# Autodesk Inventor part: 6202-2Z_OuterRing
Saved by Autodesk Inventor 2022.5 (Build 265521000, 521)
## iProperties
Created: 2024-12
Part Number: 6202-2Z_OuterRing
Material: Generic
Document SubType Name: Modeling
Designer: AdminForWorker
Density: 1 g/cm^3
Appearance: Default
Title: 6202-2Z_OuterRing
Author: AdminForWorker
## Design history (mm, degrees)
feature "Body1"
body "Solid1"
